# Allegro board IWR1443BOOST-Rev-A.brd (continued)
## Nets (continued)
UNNAMED_25_P87524BRNFRQ1ES22P_4: R146.2 U8.5(SCL)
UNNAMED_25_P87524BRNFRQ1ES22P_5: R144.2 U8.6(SDA)
UNNAMED_25_P87524BRNFRQ1ES22PRE: R148.1 U8.15(EN2)
UNNAMED_33_CAPNONPOLARIZED_I75_: C16.2 R78.1 U3.3(VCC)
UNNAMED_33_CAPNONPOLARIZED_I77_: C24.2 R85.1 R87.2
UNNAMED_33_OSTTE030161_I26_1: J3.1 R85.2 U3.7(CANH)
UNNAMED_33_OSTTE030161_I26_3: J3.3 R87.1 U3.6(CANL)
UNNAMED_33_RESISTOR_I42_1: R86.1 R177.1 R178.2 U3.8(STB)
UNNAMED_34_1050170001_I95_1: J8.1 R161.1
UNNAMED_34_1050170001_I95_5: J8.5 R175.2
UNNAMED_34_1050170001_I95_G1: J8.G1 J8.G2 J8.G3 J8.G4 R174.2 U10.5(IO4)
UNNAMED_34_CAPNONPOLARIZED_I11_: C78.1 R156.1 R157.2 U9.5(FB)
UNNAMED_34_CAPNONPOLARIZED_I75_: C79.2 C80.2 R176.1 U9.1(IN1) U9.2(IN2)
UNNAMED_35_CAPNONPOLARIZED_I121: C49.2 R134.1 U6.68(VBAT)
UNNAMED_35_CAPNONPOLARIZED_I122: C70.2 U6.89(OSC1) Y2.3
UNNAMED_35_CAPNONPOLARIZED_I123: C63.2 U6.88(OSC0) Y2.1
UNNAMED_35_CAPNONPOLARIZED_I137: C71.2 R154.1 U6.96(PB1)
UNNAMED_35_CAPNONPOLARIZED_I139: C66.2 C67.2 R140.1 U6.9(VREFA+) U7.1(C)
UNNAMED_35_RESISTOR_I24_2: R125.2 U6.59(RBIAS)
UNNAMED_35_RESISTOR_I29_1: R155.1 U6.70(RST*)
UNNAMED_35_RESISTOR_I77_1: R126.1 U6.62(PK5)
UNNAMED_35_RESISTOR_I78_1: R127.1 U6.60(PK7)
UNNAMED_35_RESISTOR_I79_1: R124.1 U6.61(PK6)
UNNAMED_35_RESISTOR_I80_1: R123.1 U6.63(PK4)
UNNAMED_35_RESISTOR_I83_1: R152.1 U6.95(PB0)
UNNAMED_35_RESISTOR_I124_2: R128.2 U6.33(PA0)
UNNAMED_35_RESISTOR_I125_2: R129.2 U6.34(PA1)
UNNAMED_35_RESISTOR_I138_2: R135.2 R136.2 U6.25(PC4)
UNNAMED_37_RESISTOR_I1_1: R179.1 U11.3(ALERT)
UNNAMED_37_RESISTOR_I2_2: R180.2 U11.1(SCL)
UNNAMED_37_RESISTOR_I6_2: R181.2 U11.4(ADD0)
UNNAMED_37_RESISTOR_I7_1: R182.1 U11.6(SDA)
UNNAMED_37_RESISTOR_I8_1: C84.2 R183.1 U11.5(V+)
UNNAMED_37_RESISTOR_I9_1: R184.1 U12.3(ALERT)
UNNAMED_37_RESISTOR_I10_2: R185.2 U12.1(SCL)
UNNAMED_37_RESISTOR_I13_1: R186.1 U12.6(SDA)
UNNAMED_37_RESISTOR_I14_1: C85.2 R187.1 U12.5(V+)
UNNAMED_37_RESISTOR_I15_1: R188.1 U12.4(ADD0)
XDSET_1_DM: J8.2 U6.93(PL7) U10.1(IO1)
XDSET_1_DP: J8.3 U6.94(PL6) U10.4(IO3)
XDSET_1_ID: J8.4 R152.2 U10.2(IO2)
XDSET_1_VBUS: R151.1 R154.2 R161.2 U10.6(VCC)
XDSET_TCK: R70.2 U6.35(PA2)
XDSET_TDI: R30.2 U6.38(PA5)
XDSET_TDO: R71.2 U6.37(PA4)
XDSET_TMS: R69.2 U6.36(PA3)

Pads without a net: J1 15 17 19 21 23 25 27 29 31 33 35 37 39 41 43 45 47 49; J5 4 7 20; J6 3 11; NOREF#22 1; NOREF#36 1; NOREF#47 1; NOREF#58 1; NOREF#137 1; NOREF#140 1; NOREF#147 1; NOREF#148 1; NOREF#149 1; SW1 1 3; SW2 1 3; U2 B15 D1 D15; U5 9 17; U6 2 3 4 5 6 11 12 13 14 15 18 19 20 21 22 23 24 27 29 30 31 32 41 42 43 44 45 46 49 50 53 54 56 57 65 67 71 72 73 74 75 76 77 78 81 82 83 84 85 86 91 92 97 98 99 100 102 103 104 105 106 107 108 109 110 111 112 116 117 118 119 120 121 123 124 125 126 127 128; U7 3; U9 7

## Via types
v1: diameter 0.569, hole 0.31, TOP to BOTTOM, 635 vias
v2: diameter 0.35, hole 0.15, TOP to L2, 510 vias

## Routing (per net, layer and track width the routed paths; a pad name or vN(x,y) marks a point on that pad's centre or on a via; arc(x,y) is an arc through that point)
3V3_BRD: length 165.1
  TOP w0.381: R184.2 6.18,27.36 6.34,27.2 R188.2 6.77,26.51 v1(7.11,26.17) ; R183.2 47.85,30.21 48.32,29.73 48.32,29.1 47.94,28.71 45.84,28.71 45.54,29.02 42.25,29.02 41.81,29.45 R179.2
  TOP w0.508: R187.2 7.71,26.78 v1(7.11,26.17) ; R179.2 40.15,29.78 39.59,29.22 v1(38.96,29.22)
  L3 w0.508: v1(21.2,26.28) 23.36,28.44 23.36,29.4 24.23,30.27 27.17,30.27 28.99,28.45 28.99,27.94 30.07,26.86 34.97,26.86 37.31,29.2 38.93,29.2 v1(38.96,29.22)
  BOTTOM w0.203: 22.09,32.03 23.31,32.03 U6.90 ; U6.8 8.99,32.43 9.32,32.1 9.32,32.03 9.22,31.93 8.76,31.93 8.66,32.03 U6.7 ; 6.96,35.63 U6.16 9.02,35.63 ; 6.96,40.43 U6.28 9.05,40.43 ; U6.113 15.41,28.88 15.84,29.31 16.17,29.31 ; 6.72,39.63 U6.26 9.08,39.63 ; 25.29,40.05 24.58,40.05 24.21,40.43 U6.69 21.85,40.43 21.84,40.44 ; 11.81,27.17 U6.122 11.81,29.27 ; 11.81,42.45 U6.39 11.81,45.03 ; 20.21,26.48 U6.101 20.21,29.39 ; C42.2 15.01,44.32 U6.47 ; U6.79 21.94,36.43 ; U6.51 16.61,44.9 C41.2 17.01,44.87 U6.52
  BOTTOM w0.213: 11.81,45.03 C43.2 ; 25.29,40.05 25.3,40.07 ; 11.81,42.45 11.7,42.34 ; 20.21,26.48 R155.2
  BOTTOM w0.305: 5.37,25.46 5.18,25.27 U9.4 5.47,24.23 5.84,23.86 ; U9.3 4.53,25.24 C78.2
  BOTTOM w0.508: C78.2 C77.2 6.39,25.46 ; 10.26,39.19 9.82,39.63 9.08,39.63 ; 10.26,39.19 10.26,36.02 ; 10.26,39.19 10.76,39.7 16.61,39.7 17.34,40.44 21.84,40.44 ; 22.09,32.03 21.36,32.03 20.75,31.42 20.75,29.93 20.21,29.39 19.75,29.85 16.71,29.85 16.17,29.31 ; 6.96,35.63 6.35,35.63 C61.2 6.33,35.61 R140.2 ; 9.02,35.63 9.87,35.63 10.26,36.02 ; 9.05,40.43 10.47,40.43 11.7,41.66 11.7,42.34 ; 12.08,34.19 12.08,31.49 11.81,31.21 ; 12.08,34.19 10.26,36.02 ; 12.08,34.19 12.74,34.85 17.29,34.85 18.87,36.43 21.94,36.43 ; 11.81,31.21 10.86,30.26 10.03,30.26 7.11,27.34 v1(7.11,26.17) ; 11.81,31.21 10.99,32.03 9.32,32.03 ; 11.81,31.21 11.81,29.27 ; 25.3,40.07 25.58,40.07 25.81,40.3 R134.2 ; 6.72,39.63 6.32,40.03 C50.2 6.32,40.43 6.96,40.43 ; C76.2 11.43,26.51 10.84,25.92 ; C76.2 12.45,26.51 12.9,26.06 12.9,25.81 14.55,24.15 15.97,24.15 18.3,26.48 R155.2 21,26.48 v1(21.2,26.28) ; C76.2 11.81,26.52 11.81,27.17 ; R124.2 R127.2 16.8,45.1 C41.2 C42.2 11.87,45.09 C43.2 ; 5.84,23.86 6.32,23.38 R156.2
  BOTTOM w0.889: 10.84,25.92 7.36,25.92 v1(7.11,26.17) 6.39,25.46
3V3_MON_XDS_1: length 2.7
  BOTTOM w0.305: U9.8 R159.2
  BOTTOM w0.508: R159.2 4.27,19.59 R158.2
5V_IN: length 46.9
  TOP w0.508: v1(8.05,16.56) 8.1,16.56 8.1,16.58 R100.2 ; R117.2 10.66,14.78 v1(10.66,15.6) ; FB1.2 41.57,16.4 42.23,15.74 44.65,15.74 46.25,17.34 46.25,23.69 50.03,27.47 50.5,27.47 v1(51.28,28.24) ; v1(31.39,35.05) 31.42,35.05 R78.2 ; v1(2.32,17.63) R103.2
  TOP w0.762: R176.2 1.19,20.89 1.19,18.24 1.8,17.63 v1(2.32,17.63)
  BOTTOM w0.508: v1(8.05,16.56) 8.05,16.87 6.36,18.55 5.45,18.55 4.95,18.04 4.95,17.73 4.13,16.92 3.03,16.92 v1(2.32,17.63) ; v1(51.28,28.24) 51.28,28.25 R149.2
  BOTTOM w0.762: v1(8.05,16.56) 9.01,15.6 v1(10.66,15.6) 11.53,14.73 11.53,13.87 14.07,11.33 v1(14.07,11.25)
  vias: v1(14.65,10.26) v1(15.56,9.75) v1(16.88,9.7) v1(41.22,58.9) v1(41.83,59.61) v1(42.26,58.52) v1(42.72,57.71) v1(42.82,59.36)
5V_UNREG: length 8.5
  TOP w0.635: v1(46.78,14.2) 46.36,13.77 R118.2 ; R118.2 46.03,13.18 46.88,13.18 v1(46.91,13.21) ; R118.2 45.43,14.33 46.2,15.09 v1(46.55,15.09)
  BOTTOM w0.254: v1(46.3,31.97) C68.2 46.11,31.42 45,31.42 44.9,31.32 U8.18
  vias: v1(38.2,27.17) v1(38.42,26.45) v1(38.42,25.74) v1(38.91,27.22) v1(39.16,34.79) v1(39.52,35.42) v1(39.57,27.5) v1(39.95,34.84) v1(44.33,34.81) v1(44.67,27.27) v1(45.12,34.81) v1(45.49,27.06) v1(45.51,25.74) v1(45.78,36.08) v1(45.78,35.26) v1(45.79,26.4)
+3.3VD: length 238.6
  TOP w0.152: v1(41.78,51.96) 42.68,52.85 R43.2
  TOP w0.254: R38.2 44.22,55.51 v1(44.01,55.31) ; v1(27.35,27.04) 27.98,27.67 33.85,27.67 34.27,27.25 R178.1
  TOP w0.305: U2.R13 57.64,47.17 57.64,47.17
  TOP w0.508: R16.2 v1(18.22,58.89) ; R41.2 v1(56.94,51.99) ; v1(8.1,44.06) R68.2 9.96,44.06 10.89,43.13 12.98,43.13 14.04,42.06 14.04,39.22 12.42,37.59 4.91,37.59 v1(3.44,36.12) R74.2 ; v1(6.39,24.45) 6.39,23.37 6.23,23.37 R91.2 ; R14.2 19.21,59.93 v1(19.58,60.3) ; R15.2 v1(30.91,57.25) ; U3.5 27.69,26.36 C20.2 27.68,26.65 27.35,26.99 v1(27.35,27.04) ; R37.2 v1(55.44,55.89) ; v1(58.39,47.99) 57.66,47.99 C5.2 57.64,47.17 ; R90.2 v1(8.43,23.35)
  L3 w0.508: v1(37.69,45.9) 37.69,47.33 41.78,51.42 v1(41.78,51.96) ; 9.44,23.35 9.48,23.39 ; v1(21.91,9.42) 21.94,9.39 v1(24.71,9.39) 24.89,9.58 34.42,9.58 35.76,8.24 v1(35.76,6.93) ; v1(56.94,51.99) 56.94,55.03 56.08,55.89 v1(55.44,55.89) 53.66,57.67 49.32,57.67 45.97,54.32 44.7,54.32 44.01,55 v1(44.01,55.31)
  L3 w0.635: v1(8.43,23.35) 9.44,23.35
  L3 w0.762: v1(29.36,19.32) 29.36,19.53 27.48,21.41 27.48,22.71 26.71,23.47 23.58,23.47 P4.2
  L3 w0.889: v1(6.39,24.45) 7.05,25.11 8.65,25.11 8.83,25.29 ; v1(3.44,36.12) 3.78,35.78 3.78,33.17 4.67,32.28 6.19,32.28 8.73,29.74 8.73,25.4 8.83,25.29 ; v1(27.35,27.04) 26.16,25.84 24.29,25.84 23.4,24.96 P4.2 ; 8.83,25.29 10.46,23.67
  L3 w1.016: 9.48,23.39 10.18,23.39 10.46,23.67 P3.2 13.01,23.68 P2.2 18.61,24.12 22.93,24.12 P4.2
  L4 w0.508: 43.83,56.58 43.71,56.45 42.68,56.45 41.79,55.56 41.79,54.84 42.87,53.76 42.87,53.04 v1(41.78,51.96) ; 43.83,56.58 43.83,60.99 43.17,61.65 38.4,61.65 36.37,59.61 36.37,57.58 33.6,54.81 31.77,54.81 30.8,55.78 30.8,57.15 v1(30.91,57.25) 30.02,58.14 27.58,58.14 25.58,60.14 22.89,60.14 22.43,60.59 19.87,60.59 v1(19.58,60.3) 19.58,60.25 v1(18.22,58.89) 17.69,58.37 13.05,58.37 12.54,57.86 12.54,54.25 v1(13.81,52.98) ; 43.83,56.58 44.01,56.4 v1(44.01,55.31) ; v1(56.94,51.99) 56.95,52.01 58.25,52.01 58.78,51.47 58.78,50.46 59.63,49.61 59.63,48.62
  L4 w1.016: 59.63,48.62 59.01,47.99 v1(58.39,47.99)
  BOTTOM w0.508: 36.02,7.75 36.34,7.43 36.34,7.25 ; 36.02,7.75 R171.2 ; 36.02,7.75 36.02,7.2 ; 36.34,7.25 36.07,7.25 36.02,7.2 ; 36.34,7.25 38.37,7.25 38.88,7.76 R170.2 ; v1(13.81,52.98) 13.38,52.98 12.11,51.71 11.5,51.71 9.44,49.66 9.44,47.83 7.36,45.75 7.36,45.03 8.1,44.3 v1(8.1,44.06) ; R173.2 v1(21.91,9.42) ; 36.02,7.2 v1(35.76,6.93) ; v1(29.36,19.32) 29.19,19.15 28.27,19.15 27.76,18.64 27.76,8.63 26.66,7.52 25.94,7.52 25.47,8 25.47,8.36 25.13,8.7 R172.2 v1(24.71,9.39)
  BOTTOM w0.635: R130.2 37.38,45.59 v1(37.69,45.9)
  BOTTOM w0.762: R133.2 37.34,44.69 R130.2
GND: length 161
  TOP w0.178: 61.54,41.02 U2.G7 ; U2.G7 61.54,41.02 ; U2.G7 v1(61.54,40.52) ; 61.55,42.32 U2.J7 61.51,42.32
  TOP w0.229: v1(60.13,42.5) 60.24,42.62 U2.K9
  TOP w0.254: U2.L8 60.89,43.62 ; v1(22.04,51) J1.36 ; v2(57.88,49.61) 57.88,49.19 C5.1 57.6,48.95 57.35,49.2 v2(57.35,49.56) ; v2(52.22,48.92) 52.58,48.92 C7.1 52.7,48.46 52.29,48.46 v2(52.22,48.39) ; v1(18.96,47.61) 19.04,47.69 J1.48 ; v2(52.85,33.38) 52.39,33.38 v2(52.27,33.5) ; v1(55.9,46.36) 56.19,46.36 U2.R15 ; v2(52.37,39.65) 52.85,39.65 v2(52.93,39.57) ; v2(51.33,39.37) v2(50.95,38.99) ; v2(54.63,39.6) 54.4,39.6 v2(54.04,39.24) 53.97,39.32 v2(53.49,39.32) ; v2(7.71,29.57) U12.2 ; v1(48.18,51.88) 47.66,51.88 47,52.53 U1.4 ; U2.R1 65.64,46.22 v1(65.87,46.44) ; U2.J10 59.94,42.32 v1(60.13,42.5) ; v2(50.36,35.53) 50.77,35.13 v2(50.77,35.05) ; v1(17.52,50.98) 17.54,50.98 J1.54 ; v1(20.54,50.98) 20.54,50.95 20.54,50.95 J1.42 ; v2(54.81,36.04) v2(54.81,35.48) ; J1.60 16.04,47.69 v1(15.94,47.6) ; v1(60.19,41.02) U2.G10 ; J1.24 25.04,47.68 v1(25.14,47.57) ; 54.49,48.76 54.32,48.59 v2(53.84,48.59) ; 54.49,48.76 54.12,49.12 v2(53.87,49.12) ; 54.49,48.76 C6.1 ; U10.3 52.3,13.98 v1(52.7,14.38) ; v1(26.45,47.61) 26.54,47.69 J1.18 ; J1.30 23.54,47.69 v1(23.45,47.61) ; v1(62.2,42.77) 62.01,42.97 U2.K7 U2.J7 ; v2(55.9,49.68) 55.9,49.15 C4.1 56.15,48.97 56.43,49.25 v2(56.43,49.58) ; v2(54.81,34.92) v2(54.81,34.37) ; U2.H11 59.72,41.67 v1(59.76,41.7) ; v2(55.52,36.86) v2(55.14,36.47)
  TOP w0.279: U2.K11 U2.K10 U2.L10
  TOP w0.305: v1(52.9,29.79) 53.66,29.04 U4.4
  TOP w0.381: v1(9.24,38.63) 8.9,38.98 R73.1 ; v1(6.46,46.98) C8.1 ; U2.F11 59.57,40.37 v1(59.67,40.26) ; v2(57.64,39.72) 57.71,39.78 58.88,39.78 U2.E11 ; R79.1 v1(10.34,31.29) ; J1.G3 v1(17.26,52.04) ; J1.G4 v1(13.51,52.04) ; v1(47.62,29.3) 47.61,29.3 R181.1 ; J1.G1 29.82,52.04 v1(29.48,52.37) ; J1.G2 v1(23.64,52.04) ; SW2.G v1(11.13,32.74)
  TOP w0.508: v1(33.29,62.08) 33.05,61.83 R13.1 ; C19.1 59.41,28.27 59.97,27.7 v1(59.97,27.51) ; C21.1 58.46,25.26 v1(58.92,25.26) ; v2(54.65,37.74) Y1.4 ; Q1.2 6.62,14.45 v1(7.11,13.97) ; v1(6.75,33.88) 6.75,33.91 7.09,33.91 C11.1 ; C24.1 31.81,22.79 v1(31.82,22.8) ; R81.1 52.11,31.69 52.11,31.67 v1(51.96,31.67) ; R86.2 33.83,23.04 v1(33.83,23.04) ; v1(55.39,54.81) C2.1 ; 59.36,33.18 59.36,33.13 v1(59.7,32.8) ; 59.36,33.18 v1(58.99,32.8) ; 59.36,33.18 C13.1 ; v1(9.75,26.82) C85.1 ; v1(24.48,29.03) 23.78,29.74 C71.1 ; SW1.G v1(11.16,38.51) ; v1(25.5,26.89) 26.02,26.36 C20.1 ; v1(57.94,33.64) 58.05,33.75 C12.1 ; C9.1 v2(50.68,36.68) ; C22.1 v1(50.67,24.2) ; v1(47.92,31.22) C84.1 ; R83.2 v1(50.26,26.78) ; Y1.2 v2(51.07,35.59) ; R110.1 v1(4.01,15.81) ; v2(63.57,49.78) 63.59,49.76 C3.1 ; C16.1 30.34,34.99 v1(30.4,35.05) ; R114.1 v1(13.01,13.92) ; R47.2 41.4,47.62 v1(41.7,47.93) ; R88.1 v1(26.52,24.82) ; U3.2 31.62,30.45 v1(31.62,30.45) ; C15.1 v2(52.47,34.06) ; v1(17.32,17.65) 17.59,17.92 R96.1
  TOP w0.635: C1.1 v1(56.53,57.19) ; J2.G2 v1(58.92,9.96) ; DS2.C v1(9.47,20.47) ; J2.G1 v1(55.97,10.03)
  TOP w0.762: v1(55.98,32.63) 56.34,33 C14.1
  TOP w1.016: v1(59.23,30.02) 59.29,30.08 C17.1
  BOTTOM w0.203: U6.66 22.57,41.63 v1(22.14,41.2) ; v1(15.44,29.64) 15.01,29.21 U6.114 ; U6.80 24.14,36.03 v1(24.53,35.64) ; U6.55 18.21,42.7 17.88,42.37 v1(17.6,42.37) ; U6.64 22.18,43.53 v1(22.4,43.31) ; v1(16.1,42.24) 15.92,42.24 15.41,42.75 U6.48 ; U6.10 9.49,33.23 v1(9.82,32.89) ; U6.58 19.41,42.33 v1(19.09,42.01) ; v1(9.37,36.75) 8.64,36.03 U6.17
  BOTTOM w0.254: v1(45.66,53.17) 45.16,52.67 R121.1 ; v1(44.55,53.15) 44.54,53.16 44.18,53.16 C29.1 ; U8.17 44.67,31.82 v1(44.75,31.9) ; U8.4 39.52,31.32 v1(39.36,31.48) ; U5.EP U5.3 v1(41.7,47.93)
  BOTTOM w0.279: U5.13 U5.EP
  BOTTOM w0.29: C51.1 63.76,39.78 63.54,39.55 63.52,39.55 63.51,39.55 63.06,39.55 63.05,39.55 63.03,39.55 62.78,39.3
  BOTTOM w0.305: v1(4.51,20.37) 4.53,20.37 U9.6 ; 62.78,39.3 v1(62.59,39.3)
  BOTTOM w0.508: R139.1 50.49,34.8 51.3,33.99 v1(51.3,33.73) ; C56.1 55.83,37.49 v1(55.75,37.57) ; C62.1 26.69,34.65 v1(26.92,34.42) ; C53.1 54.13,40.04 54.04,39.95 v1(53.97,39.95) ; C44.1 v1(42.59,43.72) ; v1(42.61,55.22) 42.61,55.14 42.56,55.09 R119.1 ; v1(11.5,24.79) 11.8,25.09 C76.1 ; C43.1 11.8,46.04 11.8,46.75 v1(11.8,46.76) ; v1(47.36,32.07) 47.28,31.98 C68.1 ; C80.1 v1(2.22,27.13) ; v1(39.69,51.65) 39.69,51.14 40.22,50.62 C32.1 ; v1(25.9,42.52) 25.82,42.43 C49.1 ; C67.1 v1(5.35,31.04) ; C74.1 15.71,24.82 v1(15.69,24.82) ; v1(26.92,33.55) 26.89,33.55 26.89,33.55 C64.1 ; v1(44.95,42.95) 45.04,43.04 R132.1 ; R138.1 35.89,35.89 v1(36.21,36.21) ; R123.2 22.12,46.34 v1(22.12,46.81) 21.38,46.81 20.84,46.27 R126.2 ; C63.1 29.05,33.82 v1(29.05,34.44) ; Y2.2 29.51,32.73 v1(29.51,33.12) ; U7.2 2.56,33.08 2.56,33.07 v1(2.43,33.07) ; R157.1 v1(7.67,24.08) ; v1(3.17,27.2) 3.26,27.11 C79.1 ; v1(5.35,41.2) 5.34,41.2 C50.1 ; v1(5.07,33.58) 5.35,33.3 C66.1 ; C42.1 15.65,46.07 v1(15.01,46.71) ; R158.1 4.28,18.1 v1(4.08,17.91) ; v1(40.25,43.69) 40.71,44.14 C40.1 ; v1(19.93,46.89) 19.82,46.77 R125.1 ; v1(4.72,28.02) 5.3,27.44 R153.1 ; C69.1 5.33,29.62 5.28,29.67 v1(4.64,29.67) ; C70.1 29.84,28.3 v1(29.81,28.3) ; Y2.4 26.65,29.44 v1(26.66,29.44) ; v1(5.38,36.37) 5.36,36.37 C61.1 ; C75.1 14.21,25.54 v1(13.86,25.88) ; Q2.2 v1(5.61,14.97) ; v1(16.83,46.79) 16.79,46.74 C41.1 ; C77.1 6.01,26.44 6.01,26.42 v1(6.12,26.42)
  BOTTOM w0.635: J6.4 18.55,18.9 v1(18.54,18.9) ; v1(67.15,38.61) 66.43,39.33 C52.1 ; v1(46.69,4.1) 45.93,4.86 R175.1
  BOTTOM w0.889: J4.1 v1(42.54,60.76) ; J4.2 v1(47.64,57.2)
  BOTTOM w1.016: J5.2 v1(16.96,60.53) ; J5.2 v1(16.01,62.13) ; J5.2 15.33,60.53 v1(14.85,61.01)
  vias: v1(1.7,51.66) v1(1.7,49.63) v1(1.7,47.6) v1(1.7,45.57) v1(1.7,43.54) v1(1.7,41.5) v1(3.6,23.29) v1(3.58,22.17) v1(4.21,22.73) v1(4.74,12.04) v1(4.77,23.29) v1(4.77,22.17) v1(6.78,12.04) v1(8.81,12.04) v1(9.52,31.13) v1(12.57,61.82) v1(12.87,30.33) v1(12.87,1.88) v1(15.92,33.38) v1(16.94,36.42) v1(16.94,31.34) v1(18.97,34.39) v1(18.97,31.34) v1(21,34.39) v1(25.06,1.88) v1(27.1,1.88) v1(29.03,22.89) v1(29.13,1.88) v1(35.89,52.27) v1(37.43,52.27) v1(37.71,28.33) v1(38.22,34.43) v1(40.75,24.93) v1(40.81,37.58) v1(41.21,31.55) v1(41.51,24.93) v1(41.62,37.58) v1(41.56,35.42) v1(41.61,27.21) v1(41.97,31.55) v1(42.35,24.93) v1(42.41,37.58) v1(42.45,35.42) v1(42.4,27.21) v1(42.73,31.55) v1(42.95,17.69) v1(43.11,24.93) v1(43.2,37.58) v1(43.59,49.04) v1(43.59,48.3) v1(43.59,47.55) v1(43.59,46.81) v1(43.71,18.2) v1(44.11,17.46) v1(44.29,16.51) v1(44.55,18.17) v1(44.6,49.04) v1(44.6,48.3) v1(44.6,47.55) v1(44.6,46.81) v1(45.33,18.17) v1(45.38,49.07) v1(45.48,48.3) v1(45.48,47.55) v1(45.48,46.81) v1(47.54,28) v1(47.64,35.73) v1(47.9,44.15) v1(48.23,53.87) v1(48.69,54.99) v1(49.07,53.87) v1(49.14,51.51) v1(49.07,44.17) v1(49.45,37.44) v1(49.45,36.42) v1(49.48,54.99) v1(49.88,53.87) v1(49.98,51.51) v1(50.26,55.02) v1(50.67,53.87) v1(50.79,51.51) v1(51.58,51.51) v1(53.36,45.52) v1(53.38,44.75) v1(54.15,27.63) v1(54.15,26.87) v1(54.27,44.78) v1(55.16,27.63) v1(55.16,26.87) v1(58.24,24.38) v1(58.24,23.6) v1(58.77,18.31) v1(59.43,22.28) v1(59.43,21.31) v1(59.61,24.23) v1(59.72,39.1) v1(60.24,39.79) v1(60.2,19.75) v1(60.31,35.49) v1(60.44,39.1) v1(60.62,25.25) v1(60.62,12.04) v1(60.62,10.01) v1(60.62,7.98) v1(60.62,5.94) v1(60.62,3.91) v1(60.62,1.88) v1(60.9,41.73) v1(60.9,40.19) v1(61.15,39.1) v1(61.54,39.76) v1(61.55,35.3) v1(61.64,26.26) v1(61.64,24.23) v1(61.64,21.18) v1(61.86,39.1) v1(62.31,41.87) v1(62.27,40.27) v1(62.66,25.25) v1(62.66,14.07) v1(62.66,12.04) v1(62.66,10.01) v1(62.66,7.98) v1(62.66,5.94) v1(62.66,3.91) v1(62.66,1.88) v1(62.86,35.3) v1(63.08,22.62) v1(63.67,24.23) v1(63.67,15.09) v1(63.98,63.5) v1(64.69,17.12) v1(64.69,5.94) v1(64.69,3.91) v1(64.69,1.88) v1(65.7,24.23) v1(65.98,36.35) v1(66.41,63.45) v1(66.54,32.4) v1(66.54,31.58) v1(66.72,19.15) v1(66.72,17.12) v1(66.72,15.09) v1(66.72,5.94) v1(66.72,3.91) v1(66.72,1.88) v1(67.25,46.07) v1(67.91,46.69) v1(68.14,35.56) v1(68.22,36.27) v1(68.75,19.15) v1(68.75,17.12) v1(68.75,15.09) v1(68.75,5.94) v1(68.75,3.91) v1(68.75,1.88) v1(69.46,63.45) v1(70.78,19.15) v1(70.78,17.12) v1(70.78,15.09) v1(70.78,5.94) v1(70.78,3.91) v1(70.78,1.88) v1(71.97,57.59) v1(72.31,63.45) v1(72.82,19.15) v1(72.82,17.12) v1(72.82,15.09) v1(72.82,13.06) v1(72.82,11.02) v1(72.82,8.99) v1(72.82,5.94) v1(72.82,3.91) v1(72.82,1.88) v1(73.12,60.4) v1(73.41,56.15) v1(74.14,58.17) v1(74.85,54.71) v1(74.85,19.15) v1(74.85,17.12) v1(74.85,15.09) v1(74.85,13.06) v1(74.85,11.02) v1(74.85,8.99) v1(74.85,5.94) v1(74.85,3.91) v1(74.85,1.88) v1(74.95,63.45) v1(76.28,53.27) v1(76.47,56.85) v1(76.88,19.15) v1(76.88,17.12) v1(76.88,15.09) v1(76.88,13.06) v1(76.88,11.02) v1(76.88,8.99) v1(78.71,55.42) v1(78.71,52.78) v1(78.91,19.15) v1(78.91,17.12) v1(78.91,15.09) v1(78.91,13.06) v1(78.91,11.02) v1(78.91,8.99) v2(7.18,29.58) v2(8.25,29.58) v2(43.75,61.86) v2(44.33,62.26) v2(44.33,61.46) v2(44.55,30.7) v2(44.54,30.16) v2(44.57,29.6) v2(44.86,62.38) v2(44.86,61.35) v2(45.38,62.38) v2(45.38,61.35) v2(45.91,62.38) v2(45.91,61.35) v2(46.44,62.38) v2(46.44,61.35) v2(46.96,62.38) v2(46.96,61.35) v2(47.49,62.38) v2(47.49,61.35) v2(48.01,62.38) v2(48.01,61.35) v2(48.54,62.38) v2(48.54,61.35) v2(49.06,62.38) v2(49.06,61.35) v2(49.59,62.38) v2(49.59,61.35) v2(50.12,62.38) v2(50.12,61.35) v2(50.36,36.12) v2(50.64,62.38) v2(50.64,61.35) v2(51.17,62.38) v2(51.17,61.35) v2(51.69,62.38) v2(51.69,61.35) v2(51.81,39.65) v2(52.04,34.49) v2(52.22,62.38) v2(52.22,61.35) v2(52.74,62.38) v2(52.74,61.35) v2(53.27,62.38) v2(53.27,61.35) v2(53.41,33.48) v2(53.8,62.38) v2(53.8,61.35) v2(54.32,62.38) v2(54.32,61.35) v2(54.85,62.38) v2(54.85,61.35) v2(55.37,62.38) v2(55.37,61.35) v2(55.82,59.62) v2(55.9,62.38) v2(55.9,61.35) v2(56.35,60.02) v2(56.35,59.23) v2(56.34,39.72) v2(56.34,38.42) v2(56.34,37.12) v2(56.42,62.38) v2(56.42,61.35) v2(56.95,62.38) v2(56.95,61.35) v2(56.88,60.14) v2(56.88,59.11) v2(56.99,37.77) v2(57.4,60.14) v2(57.4,59.11) v2(57.48,62.38) v2(57.48,61.35) v2(57.54,37.7) v2(57.93,60.14) v2(57.93,59.11) v2(58,62.38) v2(58,61.35) v2(58.45,60.14) v2(58.45,59.11) v2(58.53,62.38) v2(58.53,61.35) v2(59.05,62.38) v2(59.05,61.35) v2(59.03,60.14) v2(59.03,59.11) v2(59.64,62.38) v2(59.64,61.35) v2(59.62,60.14) v2(59.62,59.11) v2(60.14,60.14) v2(60.14,59.11) v2(60.16,62.38) v2(60.16,61.35) v2(60.24,37.77) v2(60.24,30.05) v2(60.42,37.25) v2(60.42,36.72) v2(60.42,36.2) v2(60.41,34.79) v2(60.4,34.25) v2(60.41,33.72) v2(60.4,33.18) v2(60.41,32.65) v2(60.41,32.12) v2(60.41,31.59) v2(60.53,38.21) v2(60.47,31.04) v2(60.5,29.57) v2(60.6,30.51) v2(60.69,62.38) v2(60.69,61.35) v2(60.67,60.14) v2(60.67,59.11) v2(60.7,29.03) v2(60.8,30) v2(61.06,29.54) v2(61.03,28.58) v2(61.21,62.38) v2(61.21,61.35) v2(61.19,60.14) v2(61.19,59.11) v2(61.26,38.21) v2(61.39,29.11) v2(61.54,37.77) v2(61.54,37.12) v2(61.54,36.59) v2(61.54,36.06) v2(61.54,34.58) v2(61.54,34.06) v2(61.54,33.53) v2(61.54,33) v2(61.54,32.48) v2(61.54,31.95) v2(61.54,31.43) v2(61.46,28.24) v2(61.74,62.26) v2(61.74,61.46) v2(61.72,60.02) v2(61.72,59.23) v2(61.66,30.89) v2(61.83,38.21) v2(61.77,28.7) v2(61.82,27.84) v2(61.91,30.42) v2(62.04,59.62) v2(62.06,61.86) v2(62.15,28.32) v2(62.19,29.98) v2(62.33,27.38) v2(62.52,29.57) v2(62.55,27.99) v2(62.56,38.21) v2(62.84,37.77) v2(62.84,37.12) v2(62.84,36.59) v2(62.84,36.06) v2(62.83,34.59) v2(62.83,34.07) v2(62.83,33.54) v2(62.83,33.01) v2(62.83,32.49) v2(62.83,31.96) v2(62.81,27.03) v2(62.91,31.42) v2(62.94,29.25) v2(62.99,27.69) v2(63.13,38.21) v2(63.14,30.86) v2(63.17,28.78) v2(63.29,26.75) v2(63.44,27.41) v2(63.52,30.43) v2(63.48,29.2) v2(63.6,28.49) v2(63.85,26.52) v2(63.86,38.21) v2(63.95,30.05) v2(63.92,28.91) v2(63.93,27.15) v2(63.96,37.26) v2(63.96,36.74) v2(63.96,36.22) v2(63.96,35.69) v2(63.97,35.02) v2(63.96,34.29) v2(63.96,33.76) v2(63.96,33.24) v2(63.96,32.71) v2(63.96,32.18) v2(64.03,31.66) v2(64.04,28.2) v2(64.14,37.77) v2(64.26,31.18) v2(64.35,44.64) v2(64.35,43.9) v2(64.35,43.34) v2(64.35,42.6) v2(64.35,42.04) v2(64.35,41.3) v2(64.35,40.74) v2(64.35,40) v2(64.41,29.74) v2(64.39,28.69) v2(64.41,26.92) v2(64.46,26.16) v2(64.51,27.96) v2(64.61,30.77) v2(64.8,44.9) v2(64.79,43.62) v2(64.79,42.32) v2(64.79,41.02) v2(64.79,39.72) v2(64.94,29.51) v2(64.89,28.51) v2(64.89,26.72) v2(65.06,30.49) v2(64.98,27.74) v2(65.07,26.01) v2(65.3,30.98) v2(65.39,44.9) v2(65.44,43.62) v2(65.44,42.32) v2(65.44,41.02) v2(65.39,39.72) v2(65.45,38.42) v2(65.39,28.37) v2(65.4,26.54) v2(65.47,29.36) v2(65.48,27.56) v2(65.58,30.37) v2(65.63,25.73) v2(65.83,30.94) v2(65.92,44.76) v2(65.92,39.87) v2(65.91,28.27) v2(65.97,43.62) v2(65.97,42.32) v2(65.97,41.02) v2(66.03,39.34) v2(66.01,38.43) v2(66.06,37.87) v2(66.06,37.24) v2(66.01,29.34) v2(66.02,27.41) v2(66,26.4) v2(66.11,30.34) v2(66.27,25.65) v2(66.45,44.8) v2(66.45,39.83) v2(66.44,38.73) v2(66.36,30.89) v2(66.43,28.21) v2(66.49,43.62) v2(66.49,42.32) v2(66.49,41.02) v2(66.54,29.29) v2(66.56,26.29) v2(66.57,39.24) v2(66.62,36.89) v2(66.62,35.99) v2(66.57,35.36) v2(66.66,30.34) v2(66.56,27.28) v2(66.67,38.05) v2(66.69,37.44) v2(66.94,45.01) v2(66.95,42.59) v2(66.95,40.74) v2(66.94,39.62) v2(66.95,30.89) v2(66.95,28.2) v2(66.9,25.62) v2(66.97,43.84) v2(67,42.03) v2(67.05,35.61) v2(67.14,37.77) v2(67.08,36.32) v2(67.08,32.97) v2(67.08,29.29) v2(67.09,27.7) v2(67.09,27.18) v2(67.14,26.2) v2(67.17,37.04) v2(67.25,32.32) v2(67.19,30.34) v2(67.35,45.34) v2(67.35,39.3) v2(67.3,31.4) v2(67.4,42.89) v2(67.45,41.69) v2(67.46,40.54) v2(67.46,35.23) v2(67.47,44.07) v2(67.51,35.94) v2(67.56,31.88) v2(67.51,30.91) v2(67.47,28.25) v2(67.62,37.31) v2(67.56,36.62) v2(67.61,32.72) v2(67.61,29.31) v2(67.61,27.67) v2(67.63,25.6) v2(67.68,33.76) v2(67.71,33.23) v2(67.72,30.34) v2(67.66,27.12) v2(67.72,26.15) v2(67.82,45.59) v2(67.82,39.04) v2(67.95,44.3) v2(67.9,43.08) v2(67.95,40.35) v2(67.94,32.31) v2(67.86,31.38) v2(67.96,41.53) v2(67.96,34.8) v2(67.99,34.19) v2(67.99,28.34) v2(68.08,37.58) v2(68.13,36.98) v2(68.14,29.39) v2(68.13,27.68) v2(68.26,33.13) v2(68.2,31.86) v2(68.16,30.95) v2(68.24,30.43) v2(68.23,27.11) v2(68.24,25.55) v2(68.35,45.64) v2(68.35,38.99) v2(68.32,33.66) v2(68.3,26.14) v2(68.45,46.18) v2(68.38,44.69) v2(68.43,44.07) v2(68.45,43.1) v2(68.42,40.57) v2(68.42,39.94) v2(68.37,32.61) v2(68.46,31.4) v2(68.49,41.52) v2(68.5,28.47) v2(68.57,37.32) v2(68.6,34.92) v2(68.57,34.12) v2(68.64,32.16) v2(68.65,29.57) v2(68.68,46.84) v2(68.68,30.73) v2(68.66,27.77) v2(68.81,38.41) v2(68.83,37.85) v2(68.83,27.11) v2(68.83,25.56) v2(68.92,47.35) v2(68.88,45.64) v2(68.9,44.69) v2(68.95,40.57) v2(68.95,39.94) v2(68.88,38.99) v2(68.95,36.58) v2(68.88,35.94) v2(68.93,35.38) v2(68.93,31.71) v2(68.94,31.19) v2(68.87,26.13) v2(69.03,46.15) v2(68.99,44.07) v2(69,43.09) v2(69.02,41.54) v2(68.97,34.48) v2(68.99,28.65) v2(69.06,28.12) v2(69.08,37.19) v2(69.11,29.82) v2(69.25,33.06) v2(69.25,27.61) v2(69.34,47.77) v2(69.35,37.65) v2(69.35,25.61) v2(69.44,47.19) v2(69.39,46.63) v2(69.4,45.64) v2(69.46,44.68) v2(69.4,38.99) v2(69.39,38.24) v2(69.39,36.18) v2(69.39,33.56) v2(69.38,27.11) v2(69.43,26.14) v2(69.54,43.96) v2(69.47,42.84) v2(69.48,41.78) v2(69.48,40.65) v2(69.48,39.94) v2(69.46,35.61) v2(69.46,34.67) v2(69.54,32.62) v2(69.53,30.13) v2(69.46,28.88) v2(69.56,48.43) v2(69.67,46.13) v2(69.72,36.83) v2(69.68,28.18) v2(69.84,47.6) v2(69.79,32.17) v2(69.76,30.6) v2(69.78,27.65) v2(69.88,48.88) v2(69.94,45.65) v2(69.96,40.88) v2(69.94,38.98) v2(69.91,37.43) v2(69.95,33.72) v2(69.91,31.66) v2(69.89,31.13) v2(69.91,29.14) v2(69.94,27.11) v2(69.87,25.61) v2(70.02,48.13) v2(70.05,47.09) v2(70.01,44.69) v2(70.01,43.74) v2(69.99,42.79) v2(70,41.84) v2(70,39.94) v2(69.97,38.16) v2(69.99,36.04) v2(69.97,35.43) v2(70,34.71) v2(70.03,28.6) v2(69.98,26.14) v2(70.1,46.48) v2(70.28,30.68) v2(70.34,29.45) v2(70.4,48.97) v2(70.5,48.44) v2(70.5,47.9) v2(70.5,47.37) v2(70.5,46.84) v2(70.53,46.18) v2(70.53,45.64) v2(70.53,44.69) v2(70.53,43.74) v2(70.53,42.79) v2(70.53,41.84) v2(70.52,40.89) v2(70.53,39.94) v2(70.5,38.99) v2(70.5,38.46) v2(70.51,37.94) v2(70.5,37.42) v2(70.52,36.89) v2(70.52,36.35) v2(70.52,35.75) v2(70.53,35.23) v2(70.53,34.7) v2(70.53,33.74) v2(70.52,33.22) v2(70.53,32.69) v2(70.52,32.17) v2(70.53,31.65) v2(70.52,28.76) v2(70.52,28.23) v2(70.5,27.71) v2(70.53,27.1) v2(70.53,26.15) v2(70.52,25.61) v2(70.74,29.79) v2(70.77,30.88) v2(71.29,30.9) v2(71.27,29.94) v2(71.81,30.91) v2(71.85,29.94) v2(72.41,30.92) v2(72.42,29.94)
VBUS_1_DETECT: length 3.8
  BOTTOM w0.203: U6.1 6.89,29.63
  BOTTOM w0.508: 6.89,29.63 6.35,29.63 C69.2 6.34,28.55 R151.2 R153.2
VDDC_1: length 18.2
  BOTTOM w0.203: 14.61,27.12 U6.115 14.61,29.73 14.54,29.8 ; 22.21,33.23 U6.87 24.31,33.23
  BOTTOM w0.508: 22.21,33.23 17.24,33.23 14.54,30.52 14.54,29.8 ; C74.2 C75.2 14.61,26.52 14.61,27.12 ; C62.2 25.22,33.56 C64.2 24.9,33.23 24.31,33.23
AR_1P3_RF1: length 2.5
  TOP w0.254: U2.G5 U2.H5 U2.J5
  TOP w0.381: U2.J5 63.44,42.32 v1(63.48,42.27) ; U2.G5 63.25,41.02 v1(63.32,41.08)
AR_1P3_RF2: length 2
  TOP w0.254: U2.D2 U2.C2
  TOP w0.381: v1(64.34,38.95) 64.45,39.07 U2.D2
  TOP w0.508: v1(64.34,38.95) 64.28,39 v1(63.53,39)
  vias: v1(46.5,50) v1(47.14,49.52) v1(47.26,50.33)
AR_1V4_APLL: length 2.1
  TOP w0.508: U2.A10 59.46,36.98 59.46,36.68
  TOP w0.635: C13.2 59.22,35.34 59.22,36.45 59.46,36.68
AR_1V4_SYNTH: length 2.5
  TOP w0.254: 57.11,36.58 U2.A13
  TOP w0.508: C14.2 56.34,35.82 57.11,36.58
AR_1V8: length 20.1
  TOP w0.254: U2.B12 58.29,37.15 57.63,36.48 57.63,35.99 ; 58.3,33.06 58.61,33.36 58.61,34.93 58.29,35.25 C12.2 ; U2.B11 58.94,37.15 58.21,36.42
  TOP w0.305: U2.F5 63.01,40.37
  TOP w0.381: 58.21,36.42 58.21,35.41 C12.2 ; v1(58.13,42.89) 58.05,42.97 U2.K13 ; U2.K5 63.07,42.97 v1(63.48,43.38) ; 63.01,40.37 v1(63.28,40.09) ; v1(58.66,39.18) 58.55,39.07 U2.D13
  TOP w0.508: 58.3,33.06 57.78,32.53 57.78,32.31 ; 57.63,35.99 57.26,35.62 57.26,32.44
  BOTTOM w0.508: C53.2 56.76,40.04 ; C53.2 56.27,40.58 ; C53.2 56.27,39.51 ; v1(63.48,43.38) 63.85,43.75 63.85,43.97 64.53,44.65 C39.2 ; C51.2 64.23,40.76 63.84,40.38 63.57,40.38 v1(63.28,40.09)
  vias: v1(56.46,31.57) v1(56.41,28.78) v1(56.58,30.66) v1(56.66,29.86) v1(57.68,30.05)
AR_ANAMUX: length 59.1
  TOP w0.102: U2.C13 58.04,38.42 v1(58.13,38.32)
  L3 w0.127: P1.3 7.74,39.8 51.89,39.8 52.9,40.82 55.31,40.82 56.05,40.08 56.05,39.11 56.84,38.32 v1(58.13,38.32)
AR_ANATEST1: length 95.5
  TOP w0.102: v1(68.09,50.9) 68.09,49 66.92,47.83 66.92,46.88 65.61,45.57 U2.P1 ; v1(22.02,17.12) 21.76,17.12 21.76,17.14 R104.2
  L3 w0.127: v1(22.02,17.12) 22.97,17.12 26.43,13.65 43.88,13.65 46.85,16.61 48.52,16.61 50.29,14.84 50.29,11.85 51.73,10.41 55.03,10.41 70.48,25.86 70.48,45.47 67.96,47.98 67.96,50.77 v1(68.09,50.9)
AR_ANATEST2: length 87.2
  TOP w0.102: U2.P2 65.12,45.89 65.12,46.34 67.13,48.35 v1(67.13,48.67) ; R94.2 24.35,17.98 v1(24.56,18.19)
  L3 w0.127: v1(24.56,18.19) 25.19,17.55 25.19,16.57 27.78,13.98 43.85,13.98 46.73,16.87 48.62,16.87 50.57,14.92 50.57,12.55 52.02,11.1 54.44,11.1 69.74,26.4 69.74,45.77 67.13,48.39 v1(67.13,48.67)
AR_ANATEST3: length 89.3
  TOP w0.102: v1(66.91,50.97) 66.11,50.16 66.11,48.11 64.47,46.47 64.47,45.9 U2.P3 ; R105.2 26.77,17.14 v1(27.1,16.81)
  L3 w0.127: v1(27.1,16.81) 27.58,16.33 27.58,16.09 29.44,14.24 43.67,14.24 46.55,17.12 48.73,17.12 50.84,15 50.84,12.63 52.13,11.35 54.3,11.35 69.46,26.52 69.46,41.52 65.23,45.75 65.23,46.93 66.08,47.78 66.08,50.14 v1(66.91,50.97)
AR_ANATEST4: length 88.1
  TOP w0.102: U2.R2 64.79,46.48 66.45,48.14 66.45,49.41 67.38,50.34 67.38,51.64 v1(67.05,51.97) ; v1(29.74,16.07) 29.74,16.48 29.08,17.14 R106.2
  L3 w0.127: v1(29.74,16.07) 30.13,16.46 34.5,16.46 36.34,14.62 43.54,14.62 46.3,17.37 48.83,17.37 51.15,15.06 51.15,12.69 52.23,11.61 54.16,11.61 69.18,26.63 69.18,40.92 64.95,45.15 64.95,47.26 65.53,47.83 65.53,50.48 67.01,51.97 v1(67.05,51.97)
AR_BSS_LOGGER: length 91.9
  TOP w0.102: U2.R4 63.49,46.4 65.15,48.06 65.15,52.08 v1(65.01,52.22) ; v1(33.34,58.98) 32.96,58.6 32.54,58.6 R31.1
  L3 w0.127: v1(65.01,52.22) 64.42,52.81 63.25,52.81 62.82,52.37 60.25,52.37 59.02,53.6 59.02,57.26 57.18,59.11 47.12,59.11 46.16,58.14 46.16,56.98 45.65,56.46 44.86,56.46 44.55,56.78 37.51,56.78 35.1,59.19 33.55,59.19 v1(33.34,58.98) 33.34,59.19 32.64,59.89 31.96,59.89 30.28,58.22 26.75,58.22 26.52,57.99 22.88,57.99 22.74,58.13 16.78,58.13 16.1,57.44 16.1,56.99 14.56,55.45 v1(13.84,55.45)
  BOTTOM w0.102: v1(13.84,55.45) 13.84,54.54 11.72,52.43 11.22,52.43 8.53,49.73 7.59,49.73 4.77,46.91 4.77,39.34 5.28,38.83 R135.1
AR_CS1: length 67.6
  TOP w0.102: R17.1 29.87,58.58 30.12,58.83 v1(30.12,59.11) ; v1(62.78,53.24) 62.78,50.98 61.42,49.62 61.42,46.33 U2.R7 ; R1.2 20.51,60.76 v1(19.67,61.61) 19.54,61.61 R14.1
  L3 w0.127: v1(19.67,61.61) 18.94,60.88 18.94,59.48 19.95,58.47 22.78,58.47 22.93,58.32 26.49,58.32 26.7,58.53 29.54,58.53 v1(30.12,59.11) 31.16,60.15 34.61,60.15 37.73,57.04 44.67,57.04 44.99,56.72 45.54,56.72 45.9,57.08 45.9,58.29 47.03,59.42 57.32,59.42 59.38,57.37 59.38,53.61 60.36,52.63 62.17,52.63 v1(62.78,53.24)
AR_GPIO_0: length 92.4
  TOP w0.102: R177.2 32.45,20.48 32.45,19.71 31.32,18.58 31.1,18.58 30.32,17.8 30.32,14.9 v1(30.35,14.87) ; U2.N4 63.49,44.56 v1(63.38,44.45)
  L3 w0.127: v1(68.6,48.39) 70.96,46.02 70.96,25.94 55,9.98 47.99,9.98 46.4,8.39 39.82,8.39 38.5,9.72 v1(37.1,9.72)
  L4 w0.152: v1(63.38,44.45) 63.42,44.49 63.42,45.24 65.98,47.8 68.01,47.8 v1(68.6,48.39)
  BOTTOM w0.102: R164.1 37.23,8.16 37.41,8.34 37.41,9.41 v1(37.1,9.72) 36.39,10.43 35.71,10.43 35.4,10.73 35.4,11.93 34.21,13.12 33.06,13.12 31.31,14.87 v1(30.35,14.87)
AR_GPIO_1: length 96.7
  TOP w0.102: v1(8.68,52.45) 8.66,52.43 8.66,45.36 7.66,44.37 7.66,41.73 R72.2 ; v1(62.01,44.39) 62.01,44.45 U2.N7 ; R9.2 24.28,60.74 v1(24.56,61.01)
  L3 w0.127: v1(24.56,61.01) 24.56,61.81 24.52,61.85 24.52,62.38 25.42,63.28 56.37,63.28 v1(66.19,53.47)
  L4 w0.152: v1(62.01,44.39) 66.19,48.57 v1(66.19,53.47)
  BOTTOM w0.102: v1(8.68,52.45) 8.96,52.73 11.7,52.73 12.59,53.62 12.59,60.43 14.98,62.81 21.61,62.81 22.22,62.2 23.9,62.2 24.58,61.52 24.58,61.11 24.48,61.01 v1(24.56,61.01)
AR_GPIO_2: length 114.6
  TOP w0.102: v1(40.68,51.63) 40.86,51.45 47.14,51.45 48.23,50.36 48.23,48.67 48.51,48.39 51.23,48.39 52.47,47.14 53.71,47.14 55.62,45.24 57.12,45.24 57.44,44.92 U2.N13 ; R8.2 37.38,59.76 v1(37.38,59.31) ; v1(2.33,13.61) R116.1 2.33,15.8 R110.2
  L3 w0.127: v1(40.68,51.63) 40.06,51 32.61,51 30.09,53.52 17.37,53.52 15.25,51.4 11.46,51.4 9.65,53.21 4.62,53.21 v1(4.18,52.78)
  BOTTOM w0.102: v1(4.18,52.78) 4.11,52.78 0.93,49.6 0.93,15.14 2.33,13.74 v1(2.33,13.61) ; v1(37.38,59.31) 40.68,56.01 v1(40.68,51.63)
AR_HOSTINTR1: length 66
  TOP w0.102: v1(63.54,52.17) 63.54,51.43 61.63,49.52 61.63,46.77 61.87,46.53 61.87,45.89 U2.P6 ; v1(32.38,59.26) 33.05,59.93 R13.2 33.74,60.39 R10.2 ; R64.2 28.9,44.74 29.1,44.93 29.1,47.12 v1(29.18,47.19)
  L3 w0.127: v1(32.38,59.26) 32.38,59.04 33.51,57.92 35.44,57.92 37.18,56.17 42.23,56.17 42.59,56.53 44.42,56.53 44.75,56.2 45.74,56.2 46.41,56.87 46.41,58.04 47.23,58.85 57.03,58.85 58.77,57.11 58.77,53.5 60.15,52.12 63.49,52.12 v1(63.54,52.17)
  BOTTOM w0.102: v1(29.18,47.19) 29.18,49.66 32.38,52.86 32.38,59.25 v1(32.38,59.26)
AR_LVDS_VALIDM: length 49
  TOP w0.102: 56.17,44.59 56.66,44.59 U2.N14
  TOP w0.132: R60.2 24.59,41.92 25.14,41.38 32.4,41.38 35.38,44.36 46.23,44.36 47.82,45.95 47.82,47.43 47.97,47.59 48.19,47.59 48.35,47.43 48.35,45.79 48.65,45.49 49.09,45.49 49.39,45.79 49.39,47.43 49.55,47.59 49.77,47.59 49.92,47.43 49.92,45.79 50.23,45.49 50.66,45.49 50.97,45.79 50.97,47.43 51.12,47.59 51.34,47.59 51.5,47.43 51.5,45.84 51.78,45.56 52.65,45.56 53.19,46.1 53.74,46.1 55.25,44.59 56.17,44.59
AR_LVDS_VALIDP: length 49
  TOP w0.132: R61.2 25.22,44.54 25.22,44.27 25.34,44.15 25.64,44.15 25.77,44.01 25.77,43.77 25.64,43.64 25.09,43.64 24.85,43.4 24.85,42.03 25.25,41.64 32.3,41.64 35.28,44.62 46.12,44.62 47.56,46.05 47.56,47.54 47.87,47.85 48.3,47.85 48.61,47.54 48.61,45.9 48.76,45.75 48.98,45.75 49.14,45.9 49.14,47.54 49.44,47.85 49.88,47.85 50.18,47.54 50.18,45.9 50.34,45.75 50.56,45.75 50.71,45.9 50.71,47.54 51.02,47.85 51.45,47.85 51.76,47.54 51.76,45.95 51.89,45.82 52.55,45.82 53.09,46.36 53.85,46.36 55.36,44.85 56.17,44.85 56.24,44.92 U2.N15
AR_LVDSCSI_0M: length 49
  TOP w0.132: R48.2 14.9,44.52 14.9,41.37 19.29,36.98 37.19,36.98 38.65,38.44 49.1,38.44 51.33,40.67 56.64,40.67 U2.G14
AR_LVDSCSI_0P: length 49
  TOP w0.132: R49.2 15.32,44.54 15.32,44.35 15.46,44.22 15.86,44.22 16,44.09 16,43.87 15.86,43.74 15.29,43.74 15.16,43.61 15.16,41.47 19.39,37.24 37.08,37.24 38.54,38.7 48.99,38.7 51.22,40.92 56.25,40.92 U2.G15
AR_LVDSCSI_1M: length 49
  TOP w0.102: U2.H14 56.66,41.34 56.16,41.34
  TOP w0.132: R50.2 16.37,44.74 16.55,44.55 16.55,40.89 16.91,40.54 17.31,40.54 17.75,40.97 17.95,40.97 18.13,40.79 18.13,40.6 17.69,40.16 17.69,39.76 19.86,37.59 36.99,37.59 38.4,39 48.76,39 51.1,41.35 56.15,41.35 56.16,41.34
AR_LVDSCSI_1P: length 49
  TOP w0.132: U2.H15 56.28,41.61 51,41.61 48.65,39.26 38.3,39.26 36.89,37.85 19.97,37.85 17.95,39.87 17.95,40.05 18.39,40.5 18.39,40.9 18.06,41.23 17.64,41.23 17.21,40.79 17.02,40.79 16.81,41 16.81,43.62 16.96,43.76 17.54,43.76 17.67,43.9 17.67,44.08 17.51,44.25 17.09,44.25 16.99,44.35 16.99,44.55 R51.2
AR_LVDSCSI_2M: length 49
  TOP w0.102: U2.K14 56.66,42.64 56.16,42.64
  TOP w0.132: 56.16,42.64 56.09,42.71 50.63,42.71 48.03,40.11 37.86,40.11 36.53,38.78 30.42,38.78 30.11,39.09 30.11,39.46 29.96,39.61 29.74,39.61 29.58,39.46 29.58,39.09 29.28,38.78 28.84,38.78 28.54,39.09 28.54,39.46 28.38,39.61 28.16,39.61 28.01,39.46 28.01,39.09 27.7,38.78 27.27,38.78 26.96,39.09 26.96,39.46 26.81,39.61 26.59,39.61 26.43,39.46 26.43,39.09 26.13,38.78 25.69,38.78 25.39,39.09 25.39,39.46 25.23,39.61 25.01,39.61 24.86,39.46 24.86,39.09 24.55,38.78 24.12,38.78 23.81,39.09 23.81,39.46 23.66,39.61 23.44,39.61 23.28,39.46 23.28,39.09 22.98,38.78 22.5,38.78 19.66,41.62 R54.2
AR_LVDSCSI_2P: length 49
  TOP w0.132: U2.K15 50.52,42.97 47.93,40.37 37.75,40.37 36.42,39.04 30.52,39.04 30.37,39.19 30.37,39.57 30.06,39.87 29.63,39.87 29.32,39.57 29.32,39.19 29.17,39.04 28.95,39.04 28.8,39.19 28.8,39.57 28.49,39.87 28.06,39.87 27.75,39.57 27.75,39.19 27.59,39.04 27.38,39.04 27.22,39.19 27.22,39.57 26.91,39.87 26.48,39.87 26.17,39.57 26.17,39.19 26.02,39.04 25.8,39.04 25.65,39.19 25.65,39.57 25.34,39.87 24.91,39.87 24.6,39.57 24.6,39.19 24.44,39.04 24.23,39.04 24.07,39.19 24.07,39.57 23.76,39.87 23.33,39.87 23.02,39.57 23.02,39.19 22.87,39.04 22.61,39.04 19.92,41.73 19.92,43.42 20.19,43.69 20.77,43.69 20.9,43.82 20.9,44.04 20.77,44.17 20.45,44.17 20.31,44.3 20.31,44.56 R55.2
AR_LVDSCSI_3M: length 49
  TOP w0.102: 56.16,43.29 56.66,43.29 U2.L14
  TOP w0.132: 56.16,43.29 56.09,43.36 50.37,43.36 47.73,40.72 43.45,40.72 43.15,41.02 43.15,41.72 43.01,41.85 42.75,41.85 42.62,41.72 42.62,41 42.33,40.72 41.85,40.72 41.57,41 41.57,41.72 41.44,41.85 41.17,41.85 41.04,41.72 41.04,41 40.76,40.72 40.28,40.72 40,41 40,41.72 39.86,41.85 39.6,41.85 39.47,41.72 39.47,41 39.18,40.72 38.71,40.72 38.42,41 38.42,41.72 38.29,41.85 38.02,41.85 37.89,41.72 37.89,41.02 36.29,39.42 31.44,39.42 30.65,40.21 22.06,40.21 21.3,40.97 R56.2
AR_LVDSCSI_3P: length 49
  TOP w0.132: R57.2 21.96,44.58 21.96,44.37 22.07,44.27 22.42,44.27 22.55,44.14 22.55,43.92 22.39,43.76 21.84,43.76 21.56,43.48 21.56,41.07 22.16,40.47 30.76,40.47 31.55,39.68 36.18,39.68 37.63,41.13 37.63,41.83 37.92,42.11 38.4,42.11 38.68,41.83 38.68,41.11 38.81,40.98 39.08,40.98 39.21,41.11 39.21,41.83 39.49,42.11 39.97,42.11 40.25,41.83 40.25,41.11 40.39,40.98 40.65,40.98 40.78,41.11 40.78,41.83 41.07,42.11 41.55,42.11 41.83,41.83 41.83,41.11 41.96,40.98 42.23,40.98 42.36,41.11 42.36,41.83 42.64,42.11 43.12,42.11 43.4,41.83 43.4,41.13 43.56,40.98 47.62,40.98 50.26,43.62 U2.L15
AR_LVDSCSI_CLKM: length 49
  TOP w0.102: 56.16,41.99 56.66,41.99 U2.J14
  TOP w0.132: 56.16,41.99 56.09,42.06 50.82,42.06 48.32,39.56 38.12,39.56 36.71,38.15 20.17,38.15 19.7,38.61 19.7,39.01 20.45,39.77 20.45,39.98 20.3,40.14 20.08,40.14 19.3,39.36 18.9,39.36 18.56,39.7 18.56,40.1 19.04,40.58 19.04,40.8 18.08,41.76 18.08,44.65 R52.2
AR_LVDSCSI_CLKP: length 49
  TOP w0.132: R53.2 18.64,44.55 18.64,44.35 18.77,44.22 19.09,44.22 19.25,44.06 19.25,43.87 19.11,43.74 18.47,43.74 18.34,43.61 18.34,41.87 19.3,40.91 19.3,40.47 18.82,39.99 18.82,39.81 19.01,39.62 19.19,39.62 19.97,40.4 20.4,40.4 20.71,40.09 20.71,39.66 19.96,38.91 19.96,38.72 20.27,38.4 36.61,38.4 38.02,39.81 48.22,39.81 50.72,42.32 U2.J15
AR_LVDSCSI_FRCLKM: length 49
  TOP w0.102: U2.M14 56.66,43.94 56.16,43.94
  TOP w0.132: R58.2 22.94,41.38 23.48,40.84 30.96,40.84 31.77,40.03 33.22,40.03 33.57,40.39 33.57,40.79 33.23,41.14 33.23,41.32 33.51,41.6 33.72,41.6 35.07,40.25 35.55,40.25 35.9,40.6 35.9,41.01 34.98,41.93 34.98,42.11 35.19,42.32 35.37,42.32 36.51,41.19 36.94,41.19 37.25,41.49 37.25,41.93 36.15,43.02 36.15,43.23 36.31,43.4 36.53,43.4 37.39,42.53 43.51,42.53 44.43,43.45 46.53,43.45 47.94,44.86 49.83,44.86 50.68,44.01 56.09,44.01 56.16,43.94
AR_LVDSCSI_FRCLKP: length 49
  TOP w0.132: R59.2 23.56,44.53 23.56,44.33 23.7,44.2 23.97,44.2 24.13,44.04 24.13,43.85 23.97,43.69 23.34,43.69 23.2,43.55 23.2,41.48 23.58,41.1 31.06,41.1 31.88,40.29 33.11,40.29 33.32,40.5 33.32,40.68 32.97,41.03 32.97,41.43 33.4,41.86 33.83,41.86 35.18,40.51 35.44,40.51 35.64,40.71 35.64,40.9 34.72,41.82 34.72,42.22 35.08,42.58 35.48,42.58 36.61,41.45 36.83,41.45 36.99,41.6 36.99,41.82 35.89,42.91 35.89,43.34 36.21,43.65 36.63,43.65 37.5,42.79 43.41,42.79 44.32,43.71 46.42,43.71 47.83,45.12 49.94,45.12 50.79,44.27 U2.M15
AR_MCUCLKOUT: length 62.2
  TOP w0.102: v1(60.55,44.46) 60.55,44.61 U2.N9 ; v1(22.09,59.77) 22.09,59.59 R25.1
  L3 w0.127: v1(22.09,59.77) 22.42,60.1 24.95,60.1 27.88,63.03 55.35,63.03 v1(65.17,53.21)
  L4 w0.127: v1(60.55,44.46) 61.53,45.44 62.31,45.44 65.65,48.78 65.65,52.74 v1(65.17,53.21)
AR_MISO1: length 53.3
  TOP w0.102: v1(61.84,54.28) 62.73,54.28 64.28,52.73 64.28,51.94 64.05,51.71 64.05,47.88 62.52,46.35 62.52,45.88 U2.P5 ; R7.2 R6.2 30.93,60.43 R11.1 30.07,60.43 v1(29.64,59.99) 29.4,60.23 R5.2
  BOTTOM w0.102: v1(61.84,54.28) 60.8,54.28 52.06,63.02 30.25,63.02 29.53,62.31 29.53,60.1 v1(29.64,59.99)
AR_MOSI1: length 64.2
  TOP w0.102: R4.2 R3.2 27.31,60.76 v1(27.1,60.97) 27.1,60.05 26.87,59.82 25.93,59.82 25.32,60.43 R12.1 24.91,60.07 24.91,59.65 25.45,59.12 R28.1 ; U2.R8 60.89,46.56 60.92,46.58 60.92,49.72 61.49,50.3 61.49,51.99 61,52.48 v1(61,55.4)
  BOTTOM w0.102: v1(61,55.4) 61.28,55.4 62.63,56.74 62.63,63.45 61.89,64.19 27.63,64.19 27.15,63.7 27.15,60.97 v1(27.1,60.97)
AR_MSS_LOGGER: length 105.3
  TOP w0.102: v1(22.68,62.76) 21.99,62.08 21.99,61.19 22.77,60.41 22.77,57.21 23.13,56.85 ; R26.1 23.49,58.55 23.13,58.19 23.13,56.85 ; 23.13,56.85 v1(23.21,56.77) ; U2.R5 62.84,46.36 64.28,47.8 64.28,48.99 64.59,49.3 v1(64.59,51.28)
  L3 w0.127: v1(23.21,56.77) 24.07,55.91 28.67,55.91 32.94,51.64 38.38,51.64 39.39,52.64 41.17,52.64 41.37,52.85 42.44,52.85 43.4,51.88 46.5,51.88 47.54,52.92 52.77,52.92 54.17,51.52 54.17,48.6 55.42,47.36 59.19,47.36 63.11,51.28 v1(64.59,51.28)
  BOTTOM w0.102: v1(22.68,62.76) 22.35,63.09 14.8,63.09 12.34,60.63 12.34,53.82 11.6,53.09 8.24,53.09 4.51,49.36 4.51,38.79 5.28,38.02 R136.1
AR_NERR_OUT: length 122.6
  TOP w0.102: R19.1 13.26,58.93 13.53,59.21 v1(14.04,59.21) ; v1(27.91,45.59) 27.91,45.1 27.55,44.74 R63.2 ; v1(6.42,20.02) 6.11,20.02 6.1,20.02 6.1,20.05 6.07,20.08 6.05,20.08 DS1.C 6.6,21.42 6.6,22.01 R91.1 ; U2.N8 60.92,44.92 61.28,44.55 61.28,43.76 v1(61.53,43.52)
  L3 w0.127: v1(6.42,20.02) 8.95,22.54 12.49,22.54 19.75,22.54 20.33,21.97 22.31,21.97 22.83,22.49 23.22,22.49 23.23,22.5 v1(25.57,22.5) ; v1(27.91,45.59) 27.57,45.59 25.82,47.34 25.82,47.87 26.19,48.24 29.5,48.24 29.71,48.03 34.52,48.03 37.47,45.09 46.7,45.09 48.01,46.41 54.35,46.41 55.03,45.73 60.18,45.73 61.28,44.63 61.28,43.76 v1(61.53,43.52)
  BOTTOM w0.102: v1(25.57,22.5) 25.73,22.5 31.43,28.21 31.43,29.85 31.17,30.11 31.17,33.92 31.84,34.59 31.84,35.54 31.33,36.05 31.33,42.64 28.38,45.59 v1(27.91,45.59) 27.3,45.59 27.15,45.45 25.69,45.45 24.45,46.68 24.45,49.28 20.3,53.43 20.3,57.34 19.85,57.78 15.46,57.78 v1(14.04,59.21)
AR_NERRIN: length 60.3
  TOP w0.102: v1(19.98,59.33) 19.88,59.23 R24.1 19.48,58.55 18.86,57.93 R16.1 ; U2.P7 61.22,45.89 61.22,49.72 61.94,50.44 61.94,53.11 v1(61.79,53.26)
  L3 w0.127: v1(61.79,53.26) 61.84,53.26 62.71,54.13 62.71,55.17 55.1,62.78 28.5,62.78 27.35,61.63 26.84,61.63 26.44,61.23 26.44,60.91 25.24,59.72 23.07,59.72 22.49,59.13 20.19,59.13 v1(19.98,59.33)
AR_NRST: length 117.6
  TOP w0.102: v1(6.6,44.65) 7.13,44.12 7.13,41.87 2.66,37.4 2.66,34.85 2.86,34.65 3.91,34.65 ; v1(1.39,22.3) 0.98,22.71 0.98,27.66 4.04,30.72 D2.A 4.04,33.83 D1.A 4.03,34.52 3.91,34.65 ; 3.91,34.65 4.1,34.84 4.11,34.84 4.14,34.87 4.14,34.88 4.4,35.14 R74.1 4.54,35.28 7.48,35.28 C11.2 8.81,35.38 SW2.4 ; v1(58.62,49.17) 58.62,49.15 58.85,48.92 58.85,47.56 57.97,46.68 57.97,45.88 58.29,45.57 U2.P12
  L3 w0.127: v1(58.62,49.17) 58.62,51.83 58.08,52.37 58.08,56.93 56.84,58.18 47.44,58.18 47.01,57.75 47.01,56.17 45.64,54.8 45.05,54.8 44.72,55.13 44.72,55.84 44.32,56.25 42.69,56.25 42.3,55.86 37.03,55.86 35.27,57.61 33,57.61 31.96,58.65 31.08,58.65 30.3,57.86 26.76,57.86 26.63,57.73 22.75,57.73 22.61,57.88 16.89,57.88 16.38,57.36 16.38,56.59 v1(14.34,54.56)
  BOTTOM w0.102: R160.1 2.05,14.69 1.39,15.35 v1(1.39,22.3) ; v1(6.6,44.65) 6.6,45.67 8.91,47.98 8.91,49.76 11.35,52.2 11.98,52.2 v1(14.34,54.56)
AR_NRST_MCU: length 55.6
  TOP w0.102: R2.2 26.48,60.76 26.61,60.9 26.61,61.53 26.89,61.81 26.89,62.65 26.05,63.49 15.49,63.49 12.41,60.41 12.41,56.92 12.74,56.59 ; R20.1 13.82,58.55 13.71,58.45 13.71,57.59 14.19,57.11 14.19,56.78 13.79,56.38 12.96,56.38 12.74,56.59 ; 12.74,56.59 12.31,56.16 12.31,53.49 11.83,53.01 8.24,53.01 6.02,50.79 6.02,44.35 6.65,43.72 6.65,42.9 5.97,42.21 5.31,42.21 1.91,38.8 R77.1
AR_NRST_XDS: length 23.4
  TOP w0.254: R80.1 1.47,31.26 1.11,31.62 1.11,38.4 5.35,42.65 5.78,42.65 v1(6.22,43.08)
  L3 w0.254: v1(6.22,43.08) 7.68,41.62 11.89,41.62 v1(12.59,42.32)
  BOTTOM w0.203: U6.40 12.21,42.7 v1(12.59,42.32)
AR_OSC_CLKOUT: length 27.2
  TOP w0.18: v1(54.02,32.69) 54.38,32.69 55.57,33.88 55.57,35.79 56.9,37.12 U2.A14 ; v1(53.61,16.04) R111.1
  L3 w0.203: v1(54.02,32.69) 54.02,29.11 52.8,27.89 52.8,16.86 v1(53.61,16.04)
AR_PMIC_CLKOUT_SOP2: length 111.7
  TOP w0.102: U2.P13 57.64,45.73 57.32,46.06 57.32,46.71 56.93,47.1 56.93,50.38 v1(56.66,50.65) ; v1(37.23,20.51) 36.82,20.1 36.82,17.54 R109.2 36.95,17.13 36.8,16.99 36.8,15.37 33.83,12.4 23.73,12.4 19.36,8.03 13.43,8.03 12.21,9.25 12.21,12.45 11.47,13.18 11.47,15.99 R98.1 R97.1
  L3 w0.127: v1(39.87,53.59) 40.74,54.46 41.94,54.46 43.89,52.51 45.9,52.51 47.54,54.15 47.54,54.75 48.45,55.65 51.51,55.65 55.03,52.13 55.47,52.13 56.66,50.94 v1(56.66,50.65)
  BOTTOM w0.102: v1(37.23,20.51) 37.23,20.78 34.16,23.85 34.16,31.7 33.55,32.31 33.55,33.05 34.16,33.66 34.16,43.08 32.01,45.23 32.01,49.89 34.93,52.81 39.09,52.81 v1(39.87,53.59)
AR_QSPI_CS: length 31.6
  TOP w0.102: v1(45.41,55.51) 45.41,55.56 45.28,55.56 45.18,55.67 R38.1 45.26,56.34 U1.1 ; U2.P8 60.57,45.88 60.57,46.56 60.71,46.7 60.71,49.9 61.06,50.24 v1(61.06,51)
  L3 w0.127: v1(61.06,51) 60.42,51.64 59.4,51.64 58.38,52.66 58.38,57.07 56.94,58.51 47.36,58.51 46.7,57.85 46.7,56.4 45.82,55.51 v1(45.41,55.51)
AR_QSPI_D0: length 12
  TOP w0.102: R45.2 54.35,50.04 55.09,50.04 56.34,51.29 57.39,51.29 58.23,52.12 59,52.12 59.2,51.92 59.2,50.51 59.68,50.02 59.68,47.38 58.94,46.64 U2.R11
AR_QSPI_D1: length 31.4
  TOP w0.102: U2.P9 59.92,45.88 59.92,46.61 60.29,46.98 60.29,52.63 58.26,54.66 58.26,57.34 57.7,57.9 44.6,57.9 43.38,56.68 43.38,55.23 43.87,54.74 R39.1
AR_QSPI_D2: length 30.2
  TOP w0.102: R42.1 43.8,53.83 R43.1 43.63,53.66 43.63,52.77 44.19,52.21 45.64,52.21 46.15,51.7 47.34,51.7 48.56,50.48 48.56,48.71 48.68,48.59 48.85,48.59 48.97,48.71 48.97,49.31 49.09,49.43 49.26,49.43 49.38,49.31 49.38,48.71 49.5,48.59 49.66,48.59 49.78,48.71 49.78,49.31 49.9,49.43 50.07,49.43 50.19,49.31 50.19,48.71 50.31,48.59 50.48,48.59 50.6,48.71 50.6,49.31 50.72,49.43 50.88,49.43 51,49.31 51,48.71 51.12,48.59 51.59,48.59 51.71,48.71 51.71,49.21 51.83,49.33 52.98,49.33 53.18,49.53 54.58,49.53 54.88,49.83 55.23,49.83 56.48,51.08 56.97,51.08 57.53,50.52 58.24,50.52 59.28,49.48 59.28,47.63 58.29,46.65 U2.R12
AR_QSPI_D3: length 30.9
  TOP w0.102: U2.P10 59.59,45.57 59.35,45.81 59.35,45.81 59.27,45.89 59.27,46.61 59.87,47.21 59.87,47.25 59.89,47.27 59.89,50.67 v1(59.63,50.93) ; v1(55.26,51.23) 55.26,51.99 R41.1 55.16,52.09 R40.2
  BOTTOM w0.102: v1(59.63,50.93) 59.63,54.95 55.71,58.88 52.19,58.88 51.53,58.22 51.53,54.56 52.24,53.85 53.46,53.85 55.26,52.04 v1(55.26,51.23)
AR_QSPI_SCLK: length 26.2
  TOP w0.102: U2.R10 59.59,46.6 60.09,47.1 60.09,52.45 59.37,53.17 59.2,53.17 58.48,52.45 58.31,52.45 58.19,52.57 58.19,52.74 58.91,53.46 58.91,53.63 58.79,53.75 58.62,53.75 57.9,53.03 57.74,53.03 57.62,53.15 57.62,53.32 58.34,54.04 58.34,54.2 58.22,54.32 58.05,54.32 57.33,53.6 57.16,53.6 57.04,53.72 57.04,53.89 57.76,54.61 57.76,54.78 57.47,55.07 56.86,55.07 55.98,54.18 55.98,53.01 56.36,52.63 57.3,52.63 57.45,52.48 57.45,51.66 57.3,51.51 56.25,51.51 55.34,50.6 54.94,50.6 R44.2
AR_RS232RX: length 143.2
  TOP w0.102: v1(20.39,23.04) 20.39,31.5 14.65,37.24 14.65,42.72 v1(10.41,46.96) 10.61,47.17 v1(10.61,49.25) ; R33.1 15.49,58.54 15.39,58.44 15.39,57.27 v1(15.44,57.23) ; v1(21,7.32) 23.06,7.32 v1(23.13,7.39) ; U2.N5 62.97,44.92 63.29,45.24 65.6,45.24 68.31,47.95 68.78,47.95 69.04,48.21 69.04,50.14 v1(69.44,50.55)
  L3 w0.127: v1(15.44,57.23) 17.76,59.55 17.76,60.6 19.4,62.24 20.1,62.24 21.58,60.76 22.96,60.76 23.84,61.63 23.84,62.07 25.32,63.54 57.01,63.54 68.5,52.06 68.5,51.49 v1(69.44,50.55)
  BOTTOM w0.102: v1(10.61,49.25) 11.09,49.25 12.59,50.75 14.36,50.75 17.19,53.58 17.19,56.01 15.97,57.23 v1(15.44,57.23) ; v1(23.13,7.39) 23.13,7.47 R166.1 24.12,7.74 R172.1 ; v1(10.41,46.96) 9.9,46.46 R129.1 ; v1(20.39,23.04) 20.39,22.35 19.4,21.36 19.4,16.18 22.24,13.34 22.24,10.54 21.43,9.73 21.43,8.31 21.22,8.1 R168.1 20.89,7.43 v1(21,7.32)
AR_RS232TX: length 147.1
  TOP w0.102: v1(13.3,59.89) 14.34,59.89 14.91,59.33 R21.1 ; v1(64.71,48.74) 64.71,47.93 63.17,46.38 63.17,45.44 62.97,45.25 62.52,45.25 U2.N6 ; v1(11.47,50.32) 10.99,50.32 9.39,48.72 v1(9.39,46.81) 9.39,45.64 11.48,43.55 13.15,43.55 14.45,42.25 14.45,37.45 13.91,36.91 13.91,30.52 19.83,24.6 19.83,22.64 20.19,22.29 21.04,22.29 v1(21.36,22.61)
  L3 w0.127: v1(13.3,59.89) 12.79,59.38 12.79,55.01 14.87,52.93 16.17,52.93 17.01,53.77 30.29,53.77 32.68,51.38 38.51,51.38 39.5,52.38 41.28,52.38 41.5,52.59 42.31,52.59 43.28,51.63 46.73,51.63 47.67,52.57 52.62,52.57 53.89,51.3 53.89,48.5 55.29,47.1 63.07,47.1 v1(64.71,48.74)
  BOTTOM w0.102: v1(21.36,22.61) 20.97,22.61 20.62,22.25 20.62,22.24 19.63,21.25 19.63,16.28 22.52,13.39 22.52,8.23 22.66,8.1 R167.1 22.55,7.74 R173.1 21.91,7.31 21.38,6.78 20.47,6.78 20.01,7.24 R169.1 ; v1(13.3,59.89) 13.3,58.57 15.36,56.52 16.35,56.52 16.95,55.92 16.95,53.66 14.29,51 12.16,51 v1(11.47,50.32) ; v1(9.39,46.81) 9.39,46.5 R128.1
AR_SCL: length 200.9
  TOP w0.102: v1(38.37,31.18) 38.45,31.1 38.45,30.24 38.93,29.76 39.52,29.76 40.52,30.76 R180.1 ; v1(69.08,52.98) 67.16,52.98 65.68,51.5 65.68,48.29 63.82,46.42 63.82,45.89 U2.P4 ; R22.1 16.84,58.55 16.94,58.45 16.94,57.32 v1(17.09,57.18) ; 34.08,28.65 36.13,30.7 v1(36.47,30.7) ; 34.08,28.65 v1(30.93,28.65) ; 34.08,28.65 34.74,28 34.74,21.71 31.4,18.38 31.2,18.38 30.52,17.7 30.52,15.35 30.97,14.9 v1(32.12,14.9) ; R185.1 9.51,29.74 9.8,29.45 v1(10.38,29.45)
  L3 w0.127: v1(36.04,9.54) 36.54,9.03 37.97,9.03 40,7 46.49,7 48.48,8.99 56.18,8.99 57.27,10.08 57.27,11.31 71.52,25.55 71.52,50.55 v1(69.08,52.98) ; v1(10.38,29.45) 10.92,29.45 12.08,28.28 21.79,28.28 22.47,28.97 22.47,29.76 23.97,31.25 35.92,31.25 v1(36.47,30.7)
  BOTTOM w0.102: 37.05,31.11 37.05,31.05 37.33,30.77 37.94,30.77 38.35,31.18 v1(38.37,31.18) ; 37.05,31.11 36.64,30.7 v1(36.47,30.7) ; 37.05,31.11 R146.1 ; v1(30.93,28.65) 30.53,29.05 30.53,33.98 29.95,34.56 29.95,41.36 30.75,42.16 30.75,42.55 28.47,44.83 25.57,44.83 23.97,46.43 23.97,48.97 23.46,49.48 20.95,49.48 17.6,52.83 17.6,56.67 v1(17.09,57.18) ; v1(36.04,9.54) 36.02,9.52 R171.1 36.36,8.77 36.52,8.61 36.52,7.94 36.7,7.76 37.56,7.76 37.92,8.12 R163.1 38.22,8.16 38.32,8.26 38.32,9.69 37.23,10.78 37.23,13.63 36.89,13.97 33.05,13.97 v1(32.12,14.9)
AR_SDA: length 195.4
  TOP w0.102: v1(69.13,51.94) 68.67,52.41 66.87,52.41 65.88,51.42 65.88,48.18 64.14,46.44 U2.R3 ; v1(18.13,57.15) 18.13,58.12 17.69,58.55 R23.1 ; v1(33.13,15.06) 32.8,15.39 31.6,15.39 31.38,15.17 31,15.17 30.75,15.43 30.75,17.54 31.35,18.15 31.46,18.15 34.94,21.62 34.94,28.55 36.9,30.52 36.9,32.06 v1(36.34,32.63) 35.98,32.26 35.98,31.77 33.85,29.64 v1(30.98,29.64) ; R182.2 45.4,32.63 45.28,32.75 41.09,32.75 40.46,32.12 40.46,31 39.41,29.96 39.03,29.96 38.65,30.34 38.65,30.72 38.88,30.95 38.88,32.02 v1(38.4,32.5) ; R186.2 9.84,27.93 v1(10.81,26.96)
  L3 w0.127: v1(41.01,7.73) 46.34,7.73 47.92,9.32 56.15,9.32 56.84,10.01 56.84,11.3 71.24,25.7 71.24,49.83 v1(69.13,51.94) ; v1(10.81,26.96) 11.04,26.96 11.63,27.55 21.56,27.55 22.8,28.79 22.8,29.63 23.88,30.71 29.91,30.71 v1(30.98,29.64)
  BOTTOM w0.102: v1(30.98,29.64) 30.94,29.68 30.94,42.02 30.98,42.06 30.98,42.67 28.52,45.13 25.68,45.13 24.22,46.6 24.22,49.05 23.56,49.71 22.63,49.71 20.07,52.26 20.07,57.24 19.79,57.52 18.5,57.52 v1(18.13,57.15) ; v1(41.01,7.73) 40.58,8.17 R162.1 39.52,8.17 38.93,8.77 R170.1 38.88,9.51 37.46,10.93 37.46,13.74 37,14.2 33.99,14.2 v1(33.13,15.06) ; 37.05,32.17 37.11,32.17 37.43,32.5 v1(38.4,32.5) ; 37.05,32.17 36.6,32.63 v1(36.34,32.63) ; 37.05,32.17 R144.1
